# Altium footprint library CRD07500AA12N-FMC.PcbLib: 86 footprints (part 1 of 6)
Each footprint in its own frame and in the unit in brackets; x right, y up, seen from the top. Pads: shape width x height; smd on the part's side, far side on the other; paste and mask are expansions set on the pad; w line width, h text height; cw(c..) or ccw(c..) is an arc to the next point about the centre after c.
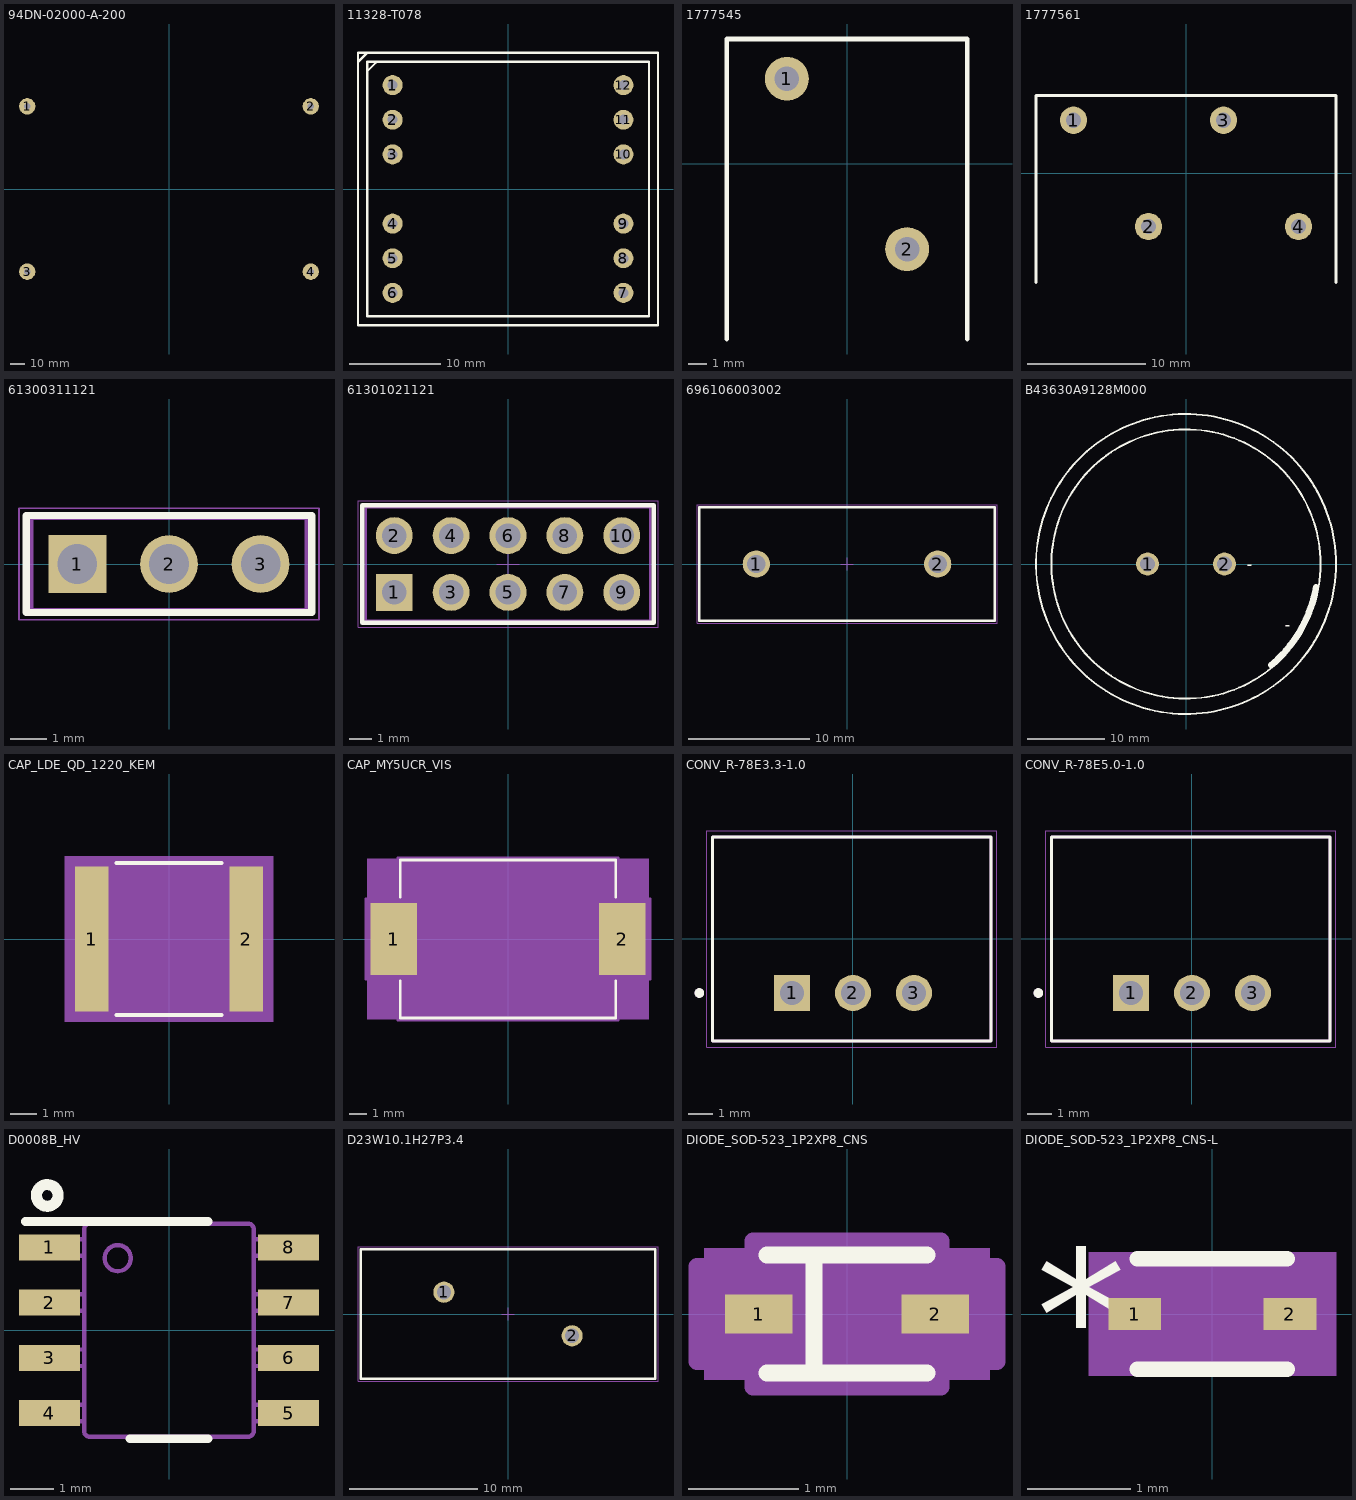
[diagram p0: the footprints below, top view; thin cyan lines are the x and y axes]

## 94DN-02000-A-200 [mm]
pads (4):
  round 11 hole 4.5: 1(-95.25,55.5) 2(95.25,55.5) 3(-95.25,-55.5) 4(95.25,-55.5)
3D body "H S Marston 94DN-02000-A-200 + Standoffs.STEP": height 52, standoff 0, extent -99.973,-61.507 100.027,61.493

## 11328-T078 [mm] "Sumida 11328-T078 Flyback transformer"
pads (12):
  round 2.2 hole 1.1: 1(-12.7,11.43) 2(-12.7,7.62) 3(-12.7,3.81) 4(-12.7,-3.81) 5(-12.7,-7.62) 6(-12.7,-11.43) 7(12.7,-11.43) 8(12.7,-7.62) 9(12.7,-3.81) 10(12.7,3.81) 11(12.7,7.62) 12(12.7,11.43)
Top Overlay:
  lines w0.254: -16.51,13.97 -15.522,14.958 ; -15.494,12.954 -14.506,13.942 ; -16.5,-15 16.5,-15 16.5,15 -16.5,15 -16.5,-15 ; -15.5,-14 15.5,-14 15.5,14 -15.5,14 -15.5,-14
3D body "PQ-26-20_6+6_tx.step": height 20.52, standoff -6.12, extent -15.004,-13.652 14.496,13.648

## 1777545 [mm]
pads (2):
  round 2.316 hole 1.3: 1(-3.175,4.5) 2(3.175,-4.5)
Top Overlay:
  lines w0.254: -6.35,-9.25 -6.35,6.6 6.35,6.6 6.35,-9.25
3D body "Phoenix Contact 1777545.stp": height 27.7, standoff -4.3, extent -6.35,-9.25 6.35,6.6

## 1777561 [mm]
pads (4):
  round 2.316 hole 1.3: 1(-9.525,4.5) 2(-3.175,-4.5) 3(3.175,4.5) 4(9.525,-4.5)
Top Overlay:
  lines w0.254: -12.7,-9.25 -12.7,6.6 12.7,6.6 12.7,-9.25
3D body "Phoenix Contact 1777561.stp": height 27.7, standoff -4.3, extent -12.7,-9.25 12.7,6.6

## 61300311121 [mm] "Pin Header, pitch 2.54 mm, THT, Vertical, single row, 3p"
height 8.54
pads (3):
  rect 1.6x1.6 hole 1.1: 1(-2.54,0)
  round 1.6 hole 1.1: 2(0,0) 3(2.54,0)
Top Overlay:
  lines w0.2: -3.96,-1.345 3.96,-1.345 3.96,1.345 -3.96,1.345 -3.96,-1.345
Mechanical 13:
  lines w0.1: -3.81,-1.27 -3.81,1.27 3.81,1.27 3.81,-1.27 -3.81,-1.27
Mechanical 15:
  lines w0.05: -0.5,0 0.5,0 ; 0,-0.5 0,0.5 ; -4.16,-1.545 -4.16,1.545 4.16,1.545 4.16,-1.545 -4.16,-1.545
3D body "61300311121.stp": height 8.57, standoff -2.97, extent -3.81,-1.27 3.81,1.27

## 61301021121 [mm] "Pin Header, pitch 2.54 mm, THT, Vertical, dual row, 10p"
height 8.54
pads (10):
  rect 1.65x1.65 hole 1.1: 1(-5.08,-1.27)
  round 1.65 hole 1.1: 2(-5.08,1.27) 3(-2.54,-1.27) 4(-2.54,1.27) 5(0,-1.27) 6(0,1.27) 7(2.54,-1.27) 8(2.54,1.27) 9(5.08,-1.27) 10(5.08,1.27)
Top Overlay:
  lines w0.2: -6.5,-2.615 -6.5,2.615 6.5,2.615 6.5,-2.615 -6.5,-2.615
Mechanical 13:
  lines w0.1: -6.35,-2.54 -6.35,2.54 6.35,2.54 6.35,-2.54 -6.35,-2.54
Mechanical 15:
  lines w0.05: -0.5,0 0.5,0 ; 0,-0.5 0,0.5 ; -6.7,-2.815 6.7,-2.815 6.7,2.815 -6.7,2.815 -6.7,-2.815
3D body "61301021121.stp": height 8.59, standoff -2.95, extent -6.35,-2.54 6.35,2.54

## 696106003002 [mm] "FUSEHOLDER BLOCKS - PCB - CLIP COVER - THT"
height 11.5
pads (2):
  round 2.25 hole 1.5: 1(-7.5,0) 2(7.5,0)
Top Overlay:
  lines w0.2: -12.2,-4.7 -12.2,4.7 12.2,4.7 12.2,-4.7 -12.2,-4.7
Mechanical 13:
  lines w0.1: -12.2,-4.7 12.2,-4.7 12.2,4.7 -12.2,4.7 -12.2,-4.7
Mechanical 15:
  lines w0.05: -0.5,0 0.5,0 ; 0,-0.5 0,0.5 ; -12.4,-4.9 -12.4,4.9 12.4,4.9 12.4,-4.9 -12.4,-4.9
3D body "Fuse Assembly.STEP": height 14.05, standoff -2.95, extent -12.2,-4.7 12.2,4.7

## B43630A9128M000 [mm] "400V 1200uF"
pads (2):
  round 3 hole 2: 1(-5,0) 2(5,0)
Top Overlay:
  circle w0.254: c0,0 r19.5
  circle w0.254: c0,0 r17.5
  lines w0.762: 11.021,-13.134 ccw(c0,0) 16.885,-2.977
  text "-" at 12.827,-8.636 h1.52
  text "-" at 7.874,-0.762 h1.52
3D body "alc40a681dl400 (bulk cap).stp": height 82.55, standoff -6.74, extent -25.456,-25.456 25.456,25.456

## CAP_LDE_QD_1220_KEM [mil]
pads (2):
  rect 49x213 smd paste+0 mask+0: 1(-113.5,0) 2(113.5,0)
Top Overlay:
  lines w6: -76.89,-111.5 76.89,-111.5 ; -76.89,111.5 76.89,111.5
Mechanical 5:
  region: 153,-121.5 -153,-121.5 -153,121.5 153,121.5
Mechanical 13:
  circle w0: c-108.5,0 r3
  lines w1: -124,-106.5 -124,106.5 ; -124,-106.5 -89,-106.5 -89,106.5 -124,106.5 ; -124,-106.5 124,-106.5 ; -124,-106.5 -124,106.5 ; -124,106.5 124,106.5 ; 124,-106.5 89,-106.5 89,106.5 124,106.5 ; 124,-106.5 124,106.5 ; 124,-106.5 124,106.5
Mechanical 15:
  region: 148,-116.5 -148,-116.5 -148,116.5 148,116.5
  lines w6: -148,-116.5 -148,116.5 148,116.5 148,-116.5 -148,-116.5
3D body "CAP_LDE_QD_1220_KEM.step": height 79.02, standoff 0, extent -124.02,-106.5 124.02,106.5

## CAP_MY5UCR_VIS [mil]
pads (2):
  rect 103x159 smd paste+0 mask+0: 1(-254,0) 2(254,0)
Top Overlay:
  lines w6: -239.5,-92.6 -239.5,-175.5 239.5,-175.5 239.5,-92.6 ; -239.5,92.6 -239.5,175.5 239.5,175.5 239.5,92.6
Mechanical 5:
  region: 313,-178 -313,-178 -313,178 313,178
Mechanical 13:
  lines w1: -234.5,-85.25 -149.25,-170.5 ; -234.5,85.25 -149.25,170.5 ; -291.5,-78.5 -234.5,-78.5 -234.5,78.5 -291.5,78.5 -291.5,-78.5 ; -234.5,-170.5 -234.5,170.5 234.5,170.5 234.5,-170.5 -234.5,-170.5 ; 234.5,-78.5 291.5,-78.5 291.5,78.5 234.5,78.5 234.5,-78.5
  text "*" at -237,-25 h50
Mechanical 15:
  region: -244.5,-89.5 -315.5,-89.5 -315.5,89.5 -244.5,89.5 -244.5,180.5 244.5,180.5 244.5,89.5 315.5,89.5 315.5,-89.5 244.5,-89.5 244.5,-180.5 -244.5,-180.5
  lines w6: -315.5,-89.5 -244.5,-89.5 -244.5,-180.5 244.5,-180.5 244.5,-89.5 315.5,-89.5 315.5,89.5 244.5,89.5 244.5,180.5 -244.5,180.5 -244.5,89.5 -315.5,89.5 -315.5,-89.5
3D body "CAP_MY5UCR_VIS.step": height 45.12, standoff 0, extent -291.5,-170.51 291.5,170.51

## CONV_R-78E3.3-1.0 [mm]
pads (3):
  rect 1.508x1.508 hole 1: 1(-2.54,-2.25)
  round 1.508 hole 1: 2(0,-2.25) 3(2.54,-2.25)
Top Overlay:
  circle w0.2: c-6.4,-2.25 r0.1
  lines w0.127: -5.85,-4.25 -5.85,4.25 5.75,4.25 5.75,-4.25 -5.85,-4.25
Top Designator:
  text ".Designator" at 7.33,0.508 h1.52
Mechanical 13:
  circle w0.2: c-6.4,-2.25 r0.1
  lines w0.127: -5.85,-4.25 -5.85,4.25 5.75,4.25 5.75,-4.25 -5.85,-4.25
Mechanical 15:
  lines w0.05: -6.1,-4.5 -6.1,4.5 6,4.5 6,-4.5 -6.1,-4.5
3D body "step_temp.STEP": height 9.9, standoff -4.6, extent -5.8,-4.25 5.8,4.25

## CONV_R-78E5.0-1.0 [mm]
pads (3):
  rect 1.508x1.508 hole 1: 1(-2.54,-2.25)
  round 1.508 hole 1: 2(0,-2.25) 3(2.54,-2.25)
Top Overlay:
  circle w0.2: c-6.4,-2.25 r0.1
  lines w0.127: -5.85,-4.25 -5.85,4.25 5.75,4.25 5.75,-4.25 -5.85,-4.25
Top Designator:
  text ".Designator" at 7.33,0.508 h1.52
Mechanical 13:
  circle w0.2: c-6.4,-2.25 r0.1
  lines w0.127: -5.85,-4.25 -5.85,4.25 5.75,4.25 5.75,-4.25 -5.85,-4.25
Mechanical 15:
  lines w0.05: -6.1,-4.5 -6.1,4.5 6,4.5 6,-4.5 -6.1,-4.5
3D body "step_temp.STEP": height 9.9, standoff -4.6, extent -5.8,-4.25 5.8,4.25

## D0008B_HV [mm]
pads (8):
  rect 1.4x0.6 smd paste+0 mask+0: 1(-2.75,1.905) 2(-2.75,0.635) 3(-2.75,-0.635) 4(-2.75,-1.905) 5(2.75,-1.905) 6(2.75,-0.635) 7(2.75,0.635) 8(2.75,1.905)
Top Overlay:
  circle w0.254: c-2.8,3.1 r0.25
  lines w0.2: -3.3,2.5 0.9,2.5 ; -0.9,-2.5 0.9,-2.5
Mechanical 13:
  lines w0.1: -2.375,-2.095 -2.375,-1.715 ; -2.375,-2.095 -2.589,-2.095 -3.002,-2.095 -3.002,-1.715 -2.589,-1.715 -2.375,-1.715 ; -2.375,-2.095 -1.995,-2.095 -1.952,-2.095 -1.952,-1.715 -1.995,-1.715 -2.375,-1.715 ; -2.375,-0.825 -2.375,-0.445 ; -2.375,-0.825 -2.589,-0.825 -3.002,-0.825 -3.002,-0.445 -2.589,-0.445 -2.375,-0.445 ; -2.375,-0.825 -1.995,-0.825 -1.952,-0.825 -1.952,-0.445 -1.995,-0.445 -2.375,-0.445 ; -2.375,0.445 -2.375,0.825 ; -2.375,0.445 -2.589,0.445 -3.002,0.445 -3.002,0.825 -2.589,0.825 -2.375,0.825 ; -2.375,0.445 -1.995,0.445 -1.952,0.445 -1.952,0.825 -1.995,0.825 -2.375,0.825 ; -2.375,1.715 -2.375,2.095 ; -2.375,1.715 -2.589,1.715 -3.002,1.715 -3.002,2.095 -2.589,2.095 -2.375,2.095 ; -2.375,1.715 -1.995,1.715 -1.952,1.715 -1.952,2.095 -1.995,2.095 -2.375,2.095 ; -0.332,-2.45 -0.182,-2.45 ; -0.332,-2.45 -0.182,-2.45 ; -0.332,-2.45 -1.825,-2.45 -1.826,-2.45 cw(c-1.825,-2.323) -1.952,-2.324 -1.952,-2.323 -1.952,2.323 -1.952,2.324 cw(c-1.825,2.323) -1.826,2.45 -1.825,2.45 -0.332,2.45 ; -0.332,2.45 -0.182,2.45 ; -0.332,2.45 -0.182,2.45 ; -0.182,-2.45 0.178,-2.45 ; -0.182,2.45 0.178,2.45 ; 0.178,-2.45 0.328,-2.45 ; 0.178,-2.45 0.328,-2.45 ; 0.178,2.45 0.328,2.45 ; 0.178,2.45 0.328,2.45 ; 0.328,-2.45 1.821,-2.45 1.822,-2.45 ccw(c1.821,-2.323) 1.948,-2.324 1.948,-2.323 1.948,2.323 1.948,2.324 ccw(c1.821,2.323) 1.822,2.45 1.821,2.45 0.328,2.45 ; 2.371,-2.095 2.371,-1.715 ; 2.371,-2.095 1.991,-2.095 1.948,-2.095 1.948,-1.715 1.991,-1.715 2.371,-1.715 ; 2.371,-2.095 2.585,-2.095 2.998,-2.095 2.998,-1.715 2.585,-1.715 2.371,-1.715 ; 2.371,-0.825 2.371,-0.445 ; 2.371,-0.825 1.991,-0.825 1.948,-0.825 1.948,-0.445 1.991,-0.445 2.371,-0.445 ; 2.371,-0.825 2.585,-0.825 2.998,-0.825 2.998,-0.445 2.585,-0.445 2.371,-0.445 ; 2.371,0.445 2.371,0.825 ; 2.371,0.445 1.991,0.445 1.948,0.445 1.948,0.825 1.991,0.825 2.371,0.825 ; 2.371,0.445 2.585,0.445 2.998,0.445 2.998,0.825 2.585,0.825 2.371,0.825 ; 2.371,1.715 2.371,2.095 ; 2.371,1.715 1.991,1.715 1.948,1.715 1.948,2.095 1.991,2.095 2.371,2.095 ; 2.371,1.715 2.585,1.715 2.998,1.715 2.998,2.095 2.585,2.095 2.371,2.095 ; -1.18,1.356 ccw(c-1.18,1.656) -1.18,1.956 ccw(c-1.18,1.656) -1.18,1.356
3D body: height 0.25, standoff 0, extent 0,0 0.254,0.254
3D body "D0008B.stp": height 1.63, standoff 0, extent -3.011,-2.451 3.011,2.451

## D23W10.1H27P3.4 [mm] "Disk Varistor, Diameter 23mm, Width 10.1mm"
height 27
pads (2):
  round 1.65 hole 1.1: 1(-5,1.7) 2(5,-1.7)
Top Overlay:
  lines w0.2: -11.5,-5.05 11.5,-5.05 11.5,5.05 -11.5,5.05 -11.5,-5.05
Top Courtyard:
  lines w0.05: -0.5,0 0.5,0 ; 0,-0.5 0,0.5 ; -11.7,-5.25 11.7,-5.25 11.7,5.25 -11.7,5.25 -11.7,-5.25
Top Component Outline:
  lines w0.1: -11.5,-5.05 -11.5,5.05 11.5,5.05 11.5,-5.05 -11.5,-5.05
Top Designator:
  text ".Designator" at -7.498,-0.5 h1.5
3D body "Wurth 820525511 Varistor - Trimmed.STEP": height 24, standoff -4.4, extent -10.7,-3.65 10.7,3.65

## DIODE_SOD-523_1P2XP8_CNS [mil]
pads (2):
  rect 24x14 smd paste+0 mask+0: 1(-31.5,0) 2(31.5,0)
Top Overlay:
  lines w5.98: -11.81,-20 -11.81,20
  lines w6: -28.5,-21 28.5,-21 ; -28.5,21 28.5,21
Mechanical 5:
  region: 51,-23.5 -51,-23.5 -51,23.5 51,23.5
Mechanical 13:
  lines w1: -23.5,-8 -15.5,-16 ; -23.5,8 -15.5,16 ; -35.5,-7 -23.5,-7 -23.5,7 -35.5,7 -35.5,-7 ; -23.5,-16 -23.5,16 23.5,16 23.5,-16 -23.5,-16 ; 23.5,-7 35.5,-7 35.5,7 23.5,7 23.5,-7
  text "*" at -26,-25 h50
Mechanical 15:
  region: -33.5,-17 -53.5,-17 -53.5,17 -33.5,17 -33.5,26 33.5,26 33.5,17 53.5,17 53.5,-17 33.5,-17 33.5,-26 -33.5,-26
  lines w6: -53.5,-17 -33.5,-17 -33.5,-26 33.5,-26 33.5,-17 53.5,-17 53.5,17 33.5,17 33.5,26 -33.5,26 -33.5,17 -53.5,17 -53.5,-17
3D body "DIODE_SOD-523_1P2XP8_CNS.step": height 31.26, standoff 0, extent -35.51,-15.98 35.51,15.98

## DIODE_SOD-523_1P2XP8_CNS-L [mil]
pads (2):
  rect 20x12 smd paste+0 mask+0: 1(-29.5,0) 2(29.5,0)
Top Overlay:
  lines w6: -28.5,-21 28.5,-21 ; -28.5,21 28.5,21
  text "*" at -67,-25 h50
Mechanical 5:
  region: 47,-23.5 -47,-23.5 -47,23.5 47,23.5
Mechanical 13:
  lines w1: -23.5,-8 -15.5,-16 ; -23.5,8 -15.5,16 ; -35.5,-7 -35.5,7 -23.5,7 -23.5,-7 -35.5,-7 ; -23.5,-16 23.5,-16 23.5,16 -23.5,16 -23.5,-16 ; 23.5,-7 23.5,7 35.5,7 35.5,-7 23.5,-7
  text "*" at -26,-25 h50
Mechanical 15:
  region: -27.5,-10 -43.5,-10 -43.5,10 -27.5,10 -27.5,20 27.5,20 27.5,10 43.5,10 43.5,-10 27.5,-10 27.5,-20 -27.5,-20
  lines w6: -43.5,-10 -43.5,10 -27.5,10 -27.5,20 27.5,20 27.5,10 43.5,10 43.5,-10 27.5,-10 27.5,-20 -27.5,-20 -27.5,-10 -43.5,-10
3D body "DIODE_SOD-523_1P2XP8_CNS.step": height 31.26, standoff 0, extent -35.51,-15.98 35.51,15.98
